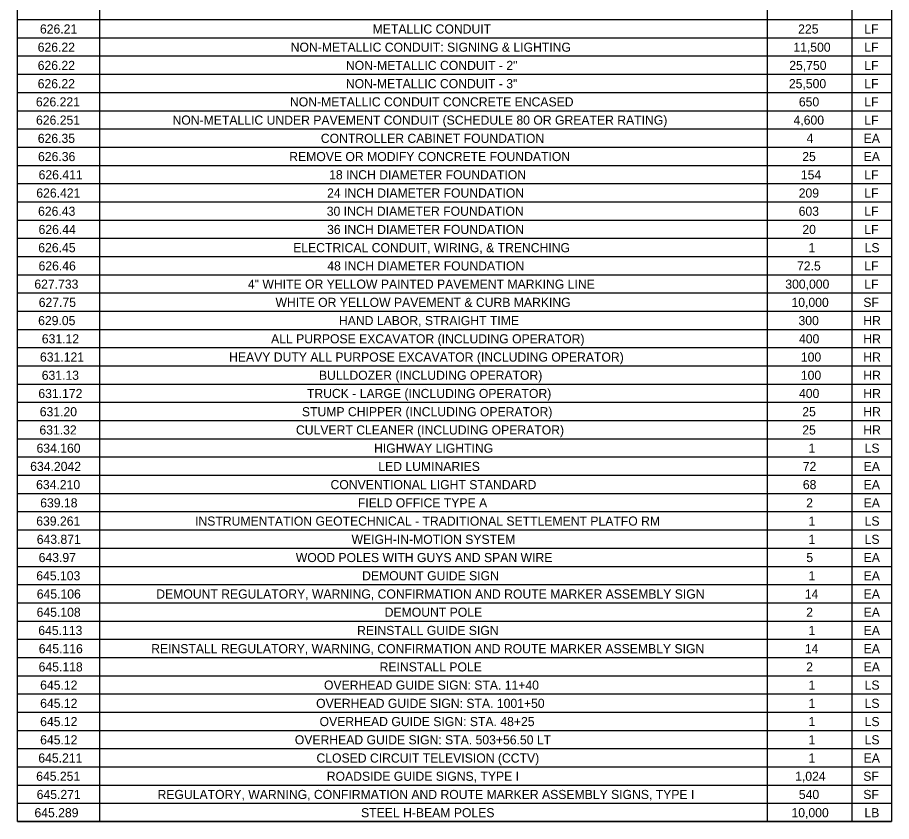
# Model space of a CAD drawing. Extents: x -18.7 to 5.6, y -2.7 to 4.
# Drawn here: x -6.23 to -5.286, y -0.822 to 0.046 of the extents above; entities that cross this region are included whole.
import ezdxf

# ---------------------------------------------------------------- set-up
doc = ezdxf.new("R2010")
doc.units = 0
doc.layers.add('ANNOTATION', color=7, linetype='Continuous')
doc.layers.add('BORDER', color=7, linetype='Continuous')

msp = doc.modelspace()

# ---------------------------------------------------------------- linework, layer by layer
at = {"layer": 'BORDER'}
for p, q in [((-6.14178, 0.89068), (-6.14178, -0.82201)), ((-5.42047, 0.89068), (-5.42047, -0.82201)), ((-5.32908, 0.89068), (-5.32908, -0.82201)), ((-6.23036, 0.04418), (-5.28608, 0.04418)), ((-6.23036, 0.02449), (-5.28608, 0.02449)), ((-6.23036, 0.00481), (-5.28608, 0.00481)), ((-6.23036, -0.01488), (-5.28608, -0.01488)), ((-6.23036, -0.03457), (-5.28608, -0.03457)), ((-6.23036, -0.05425), (-5.28608, -0.05425)), ((-6.23036, -0.07394), (-5.28608, -0.07394)), ((-6.23036, -0.09362), (-5.28608, -0.09362)), ((-6.23036, -0.11331), (-5.28608, -0.11331)), ((-6.23036, -0.133), (-5.28608, -0.133)), ((-6.23036, -0.15268), (-5.28608, -0.15268)), ((-6.23036, -0.17237), (-5.28608, -0.17237)), ((-6.23036, -0.19205), (-5.28608, -0.19205)), ((-6.23036, -0.21174), (-5.28608, -0.21174)), ((-6.23036, -0.23143), (-5.28608, -0.23143)), ((-6.23036, -0.25111), (-5.28608, -0.25111)), ((-6.23036, -0.2708), (-5.28608, -0.2708)), ((-6.23036, -0.29048), (-5.28608, -0.29048)), ((-6.23036, -0.31017), (-5.28608, -0.31017)), ((-6.23036, -0.32986), (-5.28608, -0.32986)), ((-6.23036, -0.34954), (-5.28608, -0.34954)), ((-6.23036, -0.36923), (-5.28608, -0.36923)), ((-6.23036, -0.38891), (-5.28608, -0.38891)), ((-6.23036, -0.4086), (-5.28608, -0.4086)), ((-6.23036, -0.42829), (-5.28608, -0.42829)), ((-6.23036, -0.44797), (-5.28608, -0.44797)), ((-6.23036, -0.46766), (-5.28608, -0.46766)), ((-6.23036, -0.48734), (-5.28608, -0.48734)), ((-6.23036, -0.50703), (-5.28608, -0.50703)), ((-6.23036, -0.52672), (-5.28608, -0.52672)), ((-6.23036, -0.5464), (-5.28608, -0.5464)), ((-6.23036, -0.56609), (-5.28608, -0.56609)), ((-6.23036, -0.58577), (-5.28608, -0.58577)), ((-6.23036, -0.60546), (-5.28608, -0.60546)), ((-6.23036, -0.62515), (-5.28608, -0.62515)), ((-6.23036, -0.64483), (-5.28608, -0.64483)), ((-6.23036, -0.66452), (-5.28608, -0.66452)), ((-6.23036, -0.6842), (-5.28608, -0.6842)), ((-6.23036, -0.70389), (-5.28608, -0.70389)), ((-6.23036, -0.72358), (-5.28608, -0.72358)), ((-6.23036, -0.74326), (-5.28608, -0.74326)), ((-6.23036, -0.76295), (-5.28608, -0.76295)), ((-6.23036, -0.78263), (-5.28608, -0.78263)), ((-6.23036, -0.80232), (-5.28608, -0.80232)), ((-6.23036, -0.82201), (-5.28608, -0.82201))]:
    msp.add_line(p, q, dxfattribs=at)
msp.add_lwpolyline([(-6.23036, 0.91036), (-5.28608, 0.91036), (-5.28608, -0.82201), (-6.23036, -0.82201)], close=True, dxfattribs=at)

# ---------------------------------------------------------------- texts
at = {"layer": 'ANNOTATION'}
for s, height, p in [('626.21', 0.009843, (-6.20606, 0.02909)), ('METALLIC CONDUIT', 0.009843, (-5.84666, 0.02909)), ('225', 0.009843, (-5.38693, 0.02909)), ('LF', 0.009843, (-5.31553, 0.02909)), ('626.22', 0.009843, (-6.2085, 0.0094)), ('NON-METALLIC CONDUIT: SIGNING & LIGHTING', 0.009843, (-5.93518, 0.0094)), ('11,500', 0.009843, (-5.39215, 0.0094)), ('LF', 0.009843, (-5.31553, 0.0094)), ('626.22', 0.009843, (-6.2085, -0.01028)), ('NON-METALLIC CONDUIT - 2"', 0.009843, (-5.87554, -0.01028)), ('25,750', 0.009843, (-5.39657, -0.01028)), ('LF', 0.009843, (-5.31553, -0.01028)), ('626.22', 0.009843, (-6.2085, -0.02997)), ('NON-METALLIC CONDUIT - 3"', 0.009843, (-5.87562, -0.02997)), ('25,500', 0.009843, (-5.39696, -0.02997)), ('LF', 0.009843, (-5.31553, -0.02997)), ('626.221', 0.009843, (-6.21047, -0.04966)), ('NON-METALLIC CONDUIT CONCRETE ENCASED', 0.009843, (-5.93602, -0.04966)), ('650', 0.009843, (-5.38619, -0.04966)), ('LF', 0.009843, (-5.31553, -0.04966)), ('626.251', 0.009843, (-6.21032, -0.06934)), ('NON-METALLIC UNDER PAVEMENT CONDUIT (SCHEDULE 80 OR GREATER RATING)', 0.009843, (-6.06286, -0.06934)), ('4,600', 0.009843, (-5.39192, -0.06934)), ('LF', 0.009843, (-5.31553, -0.06934)), ('626.35', 0.009843, (-6.20842, -0.08903)), ('CONTROLLER CABINET FOUNDATION', 0.009843, (-5.90264, -0.08903)), ('4', 0.00984, (-5.37782, -0.08903)), ('EA', 0.009843, (-5.31615, -0.08903)), ('626.36', 0.009843, (-6.20815, -0.10871)), ('REMOVE OR MODIFY CONCRETE FOUNDATION', 0.009843, (-5.93677, -0.10871)), ('25', 0.009843, (-5.38251, -0.10871)), ('EA', 0.009843, (-5.31615, -0.10871)), ('626.411', 0.009843, (-6.20753, -0.1284)), ('18 INCH DIAMETER FOUNDATION', 0.009843, (-5.89367, -0.1284)), ('154', 0.009843, (-5.38402, -0.1284)), ('LF', 0.009843, (-5.31553, -0.1284)), ('626.421', 0.009843, (-6.21001, -0.14809)), ('24 INCH DIAMETER FOUNDATION', 0.009843, (-5.89584, -0.14809)), ('209', 0.009843, (-5.38635, -0.14809)), ('LF', 0.009843, (-5.31553, -0.14809)), ('626.43', 0.009843, (-6.20811, -0.16777)), ('30 INCH DIAMETER FOUNDATION', 0.009843, (-5.89622, -0.16777)), ('603', 0.009843, (-5.38638, -0.16777)), ('LF', 0.009843, (-5.31553, -0.16777)), ('626.44', 0.009843, (-6.2076, -0.18746)), ('36 INCH DIAMETER FOUNDATION', 0.009843, (-5.89591, -0.18746)), ('20', 0.009843, (-5.38239, -0.18746)), ('LF', 0.009843, (-5.31553, -0.18746)), ('626.45', 0.009843, (-6.20788, -0.20714)), ('ELECTRICAL CONDUIT, WIRING, & TRENCHING', 0.009843, (-5.93252, -0.20714)), ('1', 0.00984, (-5.37581, -0.20714)), ('LS', 0.009843, (-5.31511, -0.20714)), ('626.46', 0.009843, (-6.2076, -0.22683)), ('48 INCH DIAMETER FOUNDATION', 0.009843, (-5.89568, -0.22683)), ('72.5', 0.009843, (-5.38816, -0.22683)), ('LF', 0.009843, (-5.31553, -0.22683)), ('627.733', 0.009843, (-6.21214, -0.24652)), ('4" WHITE OR YELLOW PAINTED PAVEMENT MARKING LINE', 0.009843, (-5.98142, -0.24652)), ('300,000', 0.009843, (-5.40083, -0.24652)), ('LF', 0.009843, (-5.31553, -0.24652)), ('627.75', 0.009843, (-6.20741, -0.2662)), ('WHITE OR YELLOW PAVEMENT & CURB MARKING', 0.009843, (-5.9516, -0.2662)), ('10,000', 0.009843, (-5.39416, -0.2662)), ('SF', 0.009843, (-5.31654, -0.2662)), ('629.05', 0.009843, (-6.20803, -0.28589)), ('HAND LABOR, STRAIGHT TIME', 0.009843, (-5.88307, -0.28589)), ('300', 0.009843, (-5.38658, -0.28589)), ('HR', 0.009843, (-5.31652, -0.28589)), ('631.12', 0.009843, (-6.20408, -0.30557)), ('ALL PURPOSE EXCAVATOR (INCLUDING OPERATOR)', 0.009843, (-5.95639, -0.30557)), ('400', 0.009843, (-5.38603, -0.30557)), ('HR', 0.009843, (-5.31652, -0.30557)), ('631.121', 0.009843, (-6.20605, -0.32526)), ('HEAVY DUTY ALL PURPOSE EXCAVATOR (INCLUDING OPERATOR)', 0.009843, (-6.00176, -0.32526)), ('100', 0.009843, (-5.38402, -0.32526)), ('HR', 0.009843, (-5.31652, -0.32526)), ('631.13', 0.009843, (-6.20416, -0.34495)), ('BULLDOZER (INCLUDING OPERATOR)', 0.009843, (-5.90467, -0.34495)), ('100', 0.009843, (-5.38402, -0.34495)), ('HR', 0.009843, (-5.31652, -0.34495)), ('631.172', 0.009843, (-6.2078, -0.36463)), ('TRUCK - LARGE (INCLUDING OPERATOR)', 0.009843, (-5.91764, -0.36463)), ('400', 0.009843, (-5.38603, -0.36463)), ('HR', 0.009843, (-5.31652, -0.36463)), ('631.20', 0.009843, (-6.20629, -0.38432)), ('STUMP CHIPPER (INCLUDING OPERATOR)', 0.009843, (-5.92308, -0.38432)), ('25', 0.009843, (-5.38251, -0.38432)), ('HR', 0.009843, (-5.31652, -0.38432)), ('631.32', 0.009843, (-6.20664, -0.404)), ('CULVERT CLEANER (INCLUDING OPERATOR)', 0.009843, (-5.92949, -0.404)), ('25', 0.009843, (-5.38251, -0.404)), ('HR', 0.009843, (-5.31652, -0.404)), ('634.160', 0.009843, (-6.20977, -0.42369)), ('HIGHWAY LIGHTING', 0.009843, (-5.84514, -0.42369)), ('1', 0.00984, (-5.37581, -0.42369)), ('LS', 0.009843, (-5.31511, -0.42369)), ('634.2042', 0.009843, (-6.21663, -0.44338)), ('LED LUMINARIES', 0.009843, (-5.84051, -0.44338)), ('72', 0.009843, (-5.38197, -0.44338)), ('EA', 0.009843, (-5.31615, -0.44338)), ('634.210', 0.009843, (-6.21024, -0.46306)), ('CONVENTIONAL LIGHT STANDARD', 0.009843, (-5.89215, -0.46306)), ('68', 0.009843, (-5.38189, -0.46306)), ('EA', 0.009843, (-5.31615, -0.46306)), ('639.18', 0.009843, (-6.20578, -0.48275)), ('FIELD OFFICE TYPE A', 0.009843, (-5.86261, -0.48275)), ('2', 0.00984, (-5.37825, -0.48275)), ('EA', 0.009843, (-5.31615, -0.48275)), ('639.261', 0.009843, (-6.21008, -0.50243)), ('INSTRUMENTATION GEOTECHNICAL - TRADITIONAL SETTLEMENT PLATFO RM', 0.009843, (-6.03853, -0.50243)), ('1', 0.00984, (-5.37581, -0.50243)), ('LS', 0.009843, (-5.31511, -0.50243)), ('643.871', 0.009843, (-6.20954, -0.52212)), ('WEIGH-IN-MOTION SYSTEM', 0.009843, (-5.86946, -0.52212)), ('1', 0.00984, (-5.37581, -0.52212)), ('LS', 0.009843, (-5.31511, -0.52212)), ('643.97', 0.009843, (-6.20745, -0.54181)), ('WOOD POLES WITH GUYS AND SPAN WIRE', 0.009843, (-5.92966, -0.54181)), ('5', 0.00984, (-5.37809, -0.54181)), ('EA', 0.009843, (-5.31615, -0.54181)), ('645.103', 0.009843, (-6.21005, -0.56149)), ('DEMOUNT GUIDE SIGN', 0.009843, (-5.858, -0.56149)), ('1', 0.00984, (-5.37581, -0.56149)), ('EA', 0.009843, (-5.31615, -0.56149)), ('645.106', 0.009843, (-6.20954, -0.58118)), ('DEMOUNT REGULATORY, WARNING, CONFIRMATION AND ROUTE MARKER ASSEMBLY SIGN', 0.009843, (-6.08044, -0.58118)), ('14', 0.009843, (-5.37976, -0.58118)), ('EA', 0.009843, (-5.31615, -0.58118)), ('645.108', 0.009843, (-6.20966, -0.60086)), ('DEMOUNT POLE', 0.009843, (-5.83364, -0.60086)), ('2', 0.00984, (-5.37825, -0.60086)), ('EA', 0.009843, (-5.31615, -0.60086)), ('645.113', 0.009843, (-6.20787, -0.62055)), ('REINSTALL GUIDE SIGN', 0.009843, (-5.86346, -0.62055)), ('1', 0.00984, (-5.37581, -0.62055)), ('EA', 0.009843, (-5.31615, -0.62055)), ('645.116', 0.009843, (-6.20737, -0.64024)), ('REINSTALL REGULATORY, WARNING, CONFIRMATION AND ROUTE MARKER ASSEMBLY SIGN', 0.009843, (-6.08591, -0.64024)), ('14', 0.009843, (-5.37976, -0.64024)), ('EA', 0.009843, (-5.31615, -0.64024)), ('645.118', 0.009843, (-6.20749, -0.65992)), ('REINSTALL POLE', 0.009843, (-5.8391, -0.65992)), ('2', 0.00984, (-5.37825, -0.65992)), ('EA', 0.009843, (-5.31615, -0.65992)), ('645.12', 0.009843, (-6.20586, -0.67961)), ('OVERHEAD GUIDE SIGN: STA. 11+40', 0.009843, (-5.89922, -0.67961)), ('1', 0.00984, (-5.37581, -0.67961)), ('LS', 0.009843, (-5.31511, -0.67961)), ('645.12', 0.009843, (-6.20586, -0.69929)), ('OVERHEAD GUIDE SIGN: STA. 1001+50', 0.009843, (-5.90774, -0.69929)), ('LS', 0.009843, (-5.31511, -0.69929)), ('1', 0.00984, (-5.37581, -0.69929)), ('645.12', 0.009843, (-6.20586, -0.71898)), ('OVERHEAD GUIDE SIGN: STA. 48+25', 0.009843, (-5.90399, -0.71898)), ('1', 0.00984, (-5.37581, -0.71898)), ('LS', 0.009843, (-5.31511, -0.71898)), ('645.12', 0.009843, (-6.20586, -0.73867)), ('OVERHEAD GUIDE SIGN: STA. 503+56.50 LT', 0.009843, (-5.93075, -0.73867)), ('1', 0.00984, (-5.37581, -0.73867)), ('LS', 0.009843, (-5.31511, -0.73867)), ('645.211', 0.009843, (-6.20784, -0.75835)), ('CLOSED CIRCUIT TELEVISION (CCTV)', 0.009843, (-5.90733, -0.75835)), ('1', 0.00984, (-5.37581, -0.75835)), ('EA', 0.009843, (-5.31615, -0.75835)), ('645.251', 0.009843, (-6.21016, -0.77804)), ('ROADSIDE GUIDE SIGNS, TYPE I', 0.009843, (-5.89621, -0.77804)), ('1,024', 0.009843, (-5.39021, -0.77804)), ('SF', 0.009843, (-5.31654, -0.77804)), ('645.271', 0.009843, (-6.20962, -0.79772)), ('REGULATORY, WARNING, CONFIRMATION AND ROUTE MARKER ASSEMBLY SIGNS, TYPE I', 0.009843, (-6.07904, -0.79772)), ('540', 0.009843, (-5.38619, -0.79772)), ('SF', 0.009843, (-5.31654, -0.79772)), ('645.289', 0.009843, (-6.21202, -0.81741)), ('STEEL H-BEAM POLES', 0.009843, (-5.85914, -0.81741)), ('10,000', 0.009843, (-5.39416, -0.81741)), ('LB', 0.009843, (-5.31534, -0.81741))]:
    msp.add_text(s, height=height, dxfattribs=at).set_placement(p)

doc.saveas('drawing.dxf')
